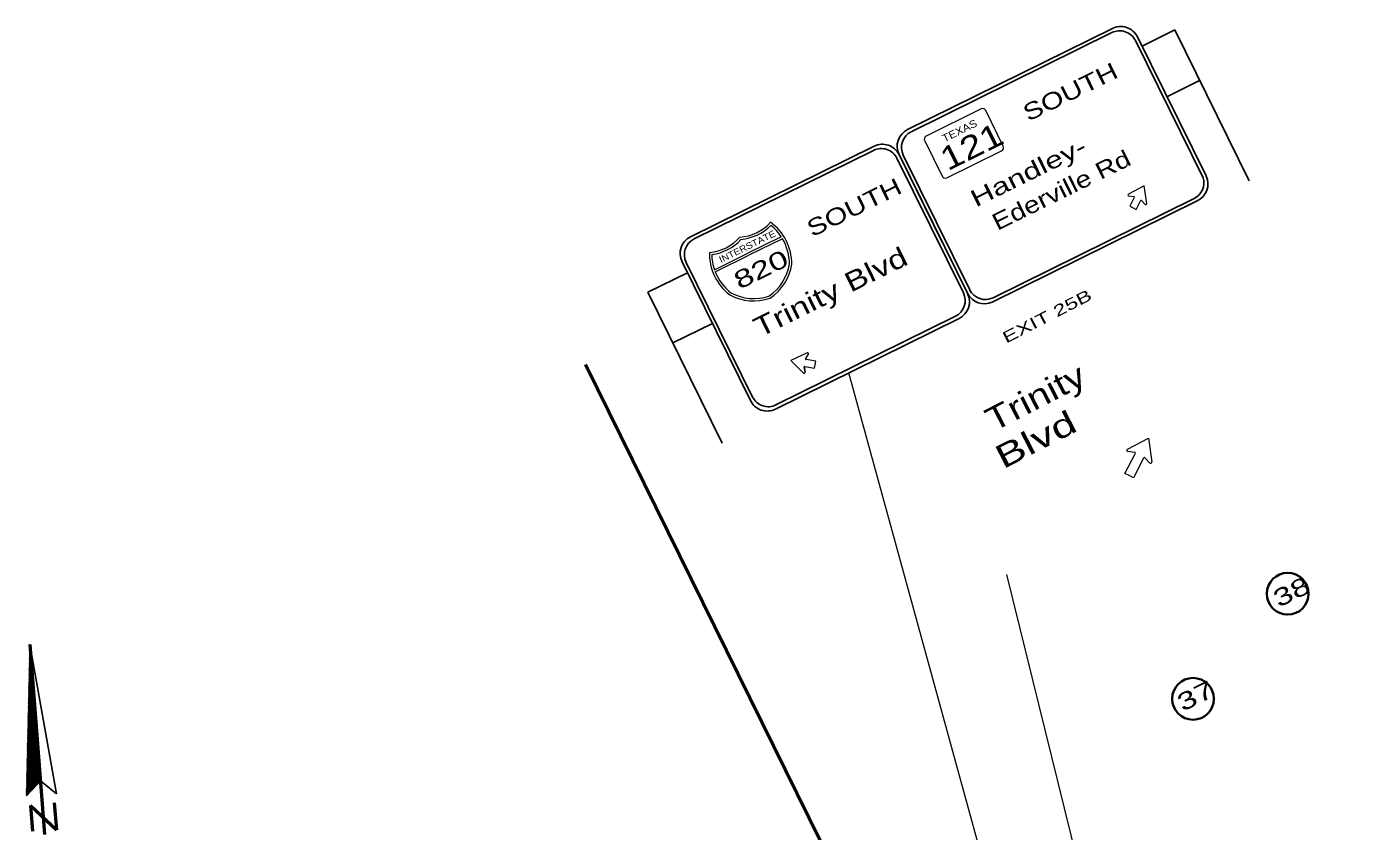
# Model space of a CAD drawing. Extents: x 2356431 to 2371438, y 6972864 to 6982525.
# Drawn here: x 2364824 to 2365891, y 6980028 to 6980677 of the extents above; entities that cross this region are included whole.
import ezdxf
from ezdxf.enums import TextEntityAlignment as Align

# ---------------------------------------------------------------- set-up
doc = ezdxf.new("R2010")
doc.units = 0
doc.header["$LTSCALE"] = 5.6
for name, color, linetype, lineweight in [('1', 7, 'Continuous', 25), ('17', 7, 'Continuous', 35), ('48', 7, 'Continuous', 25), ('53', 7, 'Continuous', 13)]:
    doc.layers.add(name, color=color, linetype=linetype, lineweight=lineweight)

msp = doc.modelspace()

# ---------------------------------------------------------------- linework, layer by layer
at = {"layer": '1'}
for p, q in [((2365699.561, 6980675.512), (2365534.335, 6980593.967)), ((2365699.121, 6980672.152), (2365537.267, 6980592.281)), ((2365772.637, 6980555.025), (2365718.004, 6980665.739)), ((2365719.704, 6980668.682), (2365774.934, 6980556.768)), ((2365723.334, 6980661.327), (2365749.68, 6980674.33)), ((2365749.68, 6980674.33), (2365809.681, 6980552.756)), ((2365743.473, 6980620.519), (2365769.82, 6980633.522)), ((2365359.337, 6980507.547), (2365507.416, 6980580.622)), ((2365362.262, 6980505.855), (2365506.979, 6980577.267)), ((2365525.812, 6980570.889), (2365579.367, 6980462.366)), ((2365527.494, 6980573.816), (2365582.881, 6980461.58)), ((2365527.494, 6980573.816), (2365562.301, 6980503.282)), ((2365530.863, 6980573.374), (2365584.421, 6980464.846)), ((2365603.297, 6980458.49), (2365765.316, 6980538.447)), ((2365602.584, 6980455.002), (2365767.8, 6980536.548)), ((2365352.536, 6980487.453), (2365407.746, 6980375.561)), ((2365409.438, 6980378.486), (2365355.874, 6980487.022)), ((2365356.9, 6980478.608), (2365325.014, 6980462.872)), ((2365325.014, 6980462.872), (2365385.015, 6980341.298)), ((2365575.911, 6980441.846), (2365427.831, 6980368.762)), ((2365572.989, 6980443.533), (2365428.272, 6980372.109)), ((2365377.036, 6980437.799), (2365345.154, 6980422.062)), ((2365451.015, 6980402.503), (2365451.716, 6980398.425))]:
    msp.add_line(p, q, dxfattribs=at)
at = {"layer": '1', "lineweight": 13}
for p, q in [((2365593.569, 6980610.607), (2365549.407, 6980588.816)), ((2365611.46, 6980580.685), (2365597.331, 6980609.33)), ((2365548.134, 6980585.048), (2365562.262, 6980556.405)), ((2365566.03, 6980555.132), (2365610.188, 6980576.918)), ((2365432.468, 6980507.644), (2365405.567, 6980494.364)), ((2365433.476, 6980506.029), (2365406.406, 6980492.671)), ((2365378.668, 6980481.086), (2365405.567, 6980494.364)), ((2365379.318, 6980479.296), (2365406.406, 6980492.671)), ((2365593.998, 6980008.645), (2365486.909, 6980397.919)), ((2365727.493, 6979776.865), (2365614.297, 6980235.555)), ((2364826.68, 6980173.822), (2364827.153, 6980174.375)), ((2364826.692, 6980174.318), (2364827.122, 6980174.817)), ((2364826.702, 6980174.816), (2364827.086, 6980175.262)), ((2364826.714, 6980175.312), (2364827.051, 6980175.706)), ((2364826.726, 6980175.81), (2364827.017, 6980176.151)), ((2364826.736, 6980176.308), (2364826.982, 6980176.594)), ((2364826.747, 6980176.805), (2364826.951, 6980177.038)), ((2364826.76, 6980177.298), (2364826.913, 6980177.483)), ((2364826.771, 6980177.799), (2364826.882, 6980177.925)), ((2364826.783, 6980178.296), (2364826.847, 6980178.371)), ((2364826.793, 6980178.791), (2364826.812, 6980178.815)), ((2364826.412, 6980161.892), (2364827.974, 6980163.716)), ((2364826.422, 6980162.39), (2364827.939, 6980164.158)), ((2364826.435, 6980162.887), (2364827.906, 6980164.605)), ((2364826.445, 6980163.386), (2364827.871, 6980165.045)), ((2364826.458, 6980163.882), (2364827.838, 6980165.492)), ((2364826.469, 6980164.379), (2364827.804, 6980165.935)), ((2364826.477, 6980164.875), (2364827.769, 6980166.38)), ((2364826.49, 6980165.371), (2364827.735, 6980166.824)), ((2364826.502, 6980165.869), (2364827.7, 6980167.269)), ((2364826.514, 6980166.365), (2364827.666, 6980167.714)), ((2364826.525, 6980166.863), (2364827.631, 6980168.158)), ((2364826.536, 6980167.362), (2364827.599, 6980168.601)), ((2364826.545, 6980167.858), (2364827.565, 6980169.046)), ((2364826.559, 6980168.356), (2364827.529, 6980169.486)), ((2364826.569, 6980168.853), (2364827.496, 6980169.936)), ((2364826.581, 6980169.349), (2364827.46, 6980170.377)), ((2364826.588, 6980169.846), (2364827.427, 6980170.823)), ((2364826.603, 6980170.343), (2364827.392, 6980171.265)), ((2364826.614, 6980170.841), (2364827.36, 6980171.709)), ((2364826.624, 6980171.339), (2364827.325, 6980172.154)), ((2364826.636, 6980171.836), (2364827.29, 6980172.596)), ((2364826.649, 6980172.334), (2364827.257, 6980173.042)), ((2364826.658, 6980172.83), (2364827.221, 6980173.486)), ((2364826.669, 6980173.326), (2364827.189, 6980173.931)), ((2364826.142, 6980149.964), (2364828.794, 6980153.057)), ((2364826.154, 6980150.462), (2364828.759, 6980153.502)), ((2364826.164, 6980150.961), (2364828.725, 6980153.946)), ((2364826.178, 6980151.456), (2364828.692, 6980154.389)), ((2364826.188, 6980151.952), (2364828.656, 6980154.835)), ((2364826.2, 6980152.449), (2364828.623, 6980155.278)), ((2364826.21, 6980152.947), (2364828.59, 6980155.723)), ((2364826.222, 6980153.445), (2364828.555, 6980156.165)), ((2364826.233, 6980153.943), (2364828.52, 6980156.609)), ((2364826.244, 6980154.44), (2364828.486, 6980157.057)), ((2364826.256, 6980154.936), (2364828.453, 6980157.498)), ((2364826.267, 6980155.432), (2364828.417, 6980157.943)), ((2364826.277, 6980155.931), (2364828.385, 6980158.385)), ((2364826.288, 6980156.424), (2364828.349, 6980158.83)), ((2364826.299, 6980156.923), (2364828.316, 6980159.275)), ((2364826.313, 6980157.419), (2364828.28, 6980159.718)), ((2364826.322, 6980157.918), (2364828.247, 6980160.162)), ((2364826.335, 6980158.416), (2364828.214, 6980160.608)), ((2364826.344, 6980158.913), (2364828.178, 6980161.051)), ((2364826.356, 6980159.409), (2364828.145, 6980161.496)), ((2364826.367, 6980159.905), (2364828.11, 6980161.939)), ((2364826.38, 6980160.404), (2364828.077, 6980162.383)), ((2364826.39, 6980160.9), (2364828.043, 6980162.828)), ((2364826.401, 6980161.396), (2364828.008, 6980163.271)), ((2364825.874, 6980138.036), (2364829.612, 6980142.398)), ((2364825.885, 6980138.533), (2364829.581, 6980142.844)), ((2364825.898, 6980139.03), (2364829.546, 6980143.286)), ((2364825.909, 6980139.527), (2364829.512, 6980143.731)), ((2364825.922, 6980140.024), (2364829.477, 6980144.174)), ((2364825.929, 6980140.522), (2364829.442, 6980144.618)), ((2364825.944, 6980141.019), (2364829.41, 6980145.062)), ((2364825.953, 6980141.517), (2364829.374, 6980145.507)), ((2364825.964, 6980142.014), (2364829.342, 6980145.95)), ((2364825.977, 6980142.511), (2364829.308, 6980146.397)), ((2364825.988, 6980143.008), (2364829.274, 6980146.837)), ((2364825.998, 6980143.505), (2364829.237, 6980147.286)), ((2364826.009, 6980143.999), (2364829.202, 6980147.728)), ((2364826.019, 6980144.497), (2364829.171, 6980148.174)), ((2364826.031, 6980144.995), (2364829.135, 6980148.615)), ((2364826.043, 6980145.492), (2364829.103, 6980149.061)), ((2364826.055, 6980145.99), (2364829.068, 6980149.505)), ((2364826.065, 6980146.486), (2364829.034, 6980149.948)), ((2364826.077, 6980146.983), (2364828.998, 6980150.392)), ((2364826.089, 6980147.479), (2364828.964, 6980150.837)), ((2364826.099, 6980147.976), (2364828.931, 6980151.28)), ((2364826.108, 6980148.471), (2364828.895, 6980151.727)), ((2364826.121, 6980148.969), (2364828.863, 6980152.168)), ((2364826.132, 6980149.467), (2364828.829, 6980152.614)), ((2364825.607, 6980126.11), (2364830.433, 6980131.738)), ((2364825.616, 6980126.605), (2364830.398, 6980132.184)), ((2364825.628, 6980127.102), (2364830.367, 6980132.629)), ((2364825.641, 6980127.598), (2364830.33, 6980133.072)), ((2364825.65, 6980128.096), (2364830.299, 6980133.516)), ((2364825.664, 6980128.593), (2364830.264, 6980133.96)), ((2364825.675, 6980129.09), (2364830.23, 6980134.406)), ((2364825.687, 6980129.585), (2364830.194, 6980134.849)), ((2364825.696, 6980130.084), (2364830.16, 6980135.294)), ((2364825.706, 6980130.58), (2364830.127, 6980135.737)), ((2364825.72, 6980131.076), (2364830.091, 6980136.181)), ((2364825.729, 6980131.575), (2364830.06, 6980136.626)), ((2364825.74, 6980132.073), (2364830.025, 6980137.068)), ((2364825.751, 6980132.571), (2364829.991, 6980137.513)), ((2364825.762, 6980133.067), (2364829.955, 6980137.957)), ((2364825.773, 6980133.564), (2364829.92, 6980138.402)), ((2364825.785, 6980134.06), (2364829.888, 6980138.847)), ((2364825.797, 6980134.557), (2364829.852, 6980139.289)), ((2364825.809, 6980135.053), (2364829.82, 6980139.734)), ((2364825.82, 6980135.552), (2364829.785, 6980140.18)), ((2364825.831, 6980136.048), (2364829.751, 6980140.622)), ((2364825.841, 6980136.543), (2364829.716, 6980141.066)), ((2364825.853, 6980137.043), (2364829.681, 6980141.508)), ((2364825.864, 6980137.541), (2364829.649, 6980141.956)), ((2364825.337, 6980114.179), (2364831.255, 6980121.082)), ((2364825.351, 6980114.676), (2364831.22, 6980121.526)), ((2364825.359, 6980115.176), (2364831.185, 6980121.969)), ((2364825.371, 6980115.67), (2364831.15, 6980122.413)), ((2364825.382, 6980116.169), (2364831.117, 6980122.858)), ((2364825.392, 6980116.667), (2364831.084, 6980123.301)), ((2364825.406, 6980117.161), (2364831.048, 6980123.748)), ((2364825.416, 6980117.658), (2364831.015, 6980124.191)), ((2364825.428, 6980118.154), (2364830.981, 6980124.635)), ((2364825.44, 6980118.653), (2364830.945, 6980125.077)), ((2364825.449, 6980119.151), (2364830.911, 6980125.525)), ((2364825.462, 6980119.647), (2364830.876, 6980125.967)), ((2364825.472, 6980120.143), (2364830.845, 6980126.409)), ((2364825.483, 6980120.641), (2364830.809, 6980126.856)), ((2364825.495, 6980121.139), (2364830.776, 6980127.299)), ((2364825.505, 6980121.634), (2364830.742, 6980127.744)), ((2364825.52, 6980122.131), (2364830.708, 6980128.186)), ((2364825.527, 6980122.629), (2364830.671, 6980128.629)), ((2364825.542, 6980123.124), (2364830.638, 6980129.078)), ((2364825.551, 6980123.624), (2364830.606, 6980129.519)), ((2364825.562, 6980124.119), (2364830.569, 6980129.963)), ((2364825.573, 6980124.619), (2364830.537, 6980130.406)), ((2364825.584, 6980125.115), (2364830.503, 6980130.85)), ((2364825.596, 6980125.61), (2364830.469, 6980131.295)), ((2364825.068, 6980102.252), (2364832.073, 6980110.421)), ((2364825.082, 6980102.748), (2364832.04, 6980110.868)), ((2364825.091, 6980103.244), (2364832.005, 6980111.31)), ((2364825.102, 6980103.741), (2364831.972, 6980111.757)), ((2364825.115, 6980104.241), (2364831.939, 6980112.2)), ((2364825.125, 6980104.733), (2364831.902, 6980112.644)), ((2364825.134, 6980105.232), (2364831.868, 6980113.087)), ((2364825.149, 6980105.731), (2364831.834, 6980113.529)), ((2364825.161, 6980106.228), (2364831.801, 6980113.977)), ((2364825.171, 6980106.722), (2364831.765, 6980114.419)), ((2364825.182, 6980107.222), (2364831.733, 6980114.864)), ((2364825.192, 6980107.719), (2364831.7, 6980115.309)), ((2364825.204, 6980108.215), (2364831.663, 6980115.753)), ((2364825.215, 6980108.713), (2364831.628, 6980116.201)), ((2364825.226, 6980109.208), (2364831.595, 6980116.641)), ((2364825.237, 6980109.706), (2364831.562, 6980117.085)), ((2364825.248, 6980110.203), (2364831.526, 6980117.53)), ((2364825.262, 6980110.702), (2364831.494, 6980117.973)), ((2364825.269, 6980111.198), (2364831.46, 6980118.418)), ((2364825.283, 6980111.695), (2364831.424, 6980118.859)), ((2364825.294, 6980112.19), (2364831.39, 6980119.307)), ((2364825.306, 6980112.689), (2364831.356, 6980119.749)), ((2364825.317, 6980113.187), (2364831.323, 6980120.195)), ((2364825.327, 6980113.683), (2364831.287, 6980120.636)), ((2364824.801, 6980090.324), (2364832.895, 6980099.765)), ((2364824.811, 6980090.818), (2364832.858, 6980100.21)), ((2364824.823, 6980091.317), (2364832.827, 6980100.652)), ((2364824.834, 6980091.813), (2364832.791, 6980101.099)), ((2364824.845, 6980092.308), (2364832.759, 6980101.542)), ((2364824.855, 6980092.807), (2364832.722, 6980101.986)), ((2364824.867, 6980093.304), (2364832.69, 6980102.431)), ((2364824.879, 6980093.802), (2364832.657, 6980102.873)), ((2364824.89, 6980094.299), (2364832.619, 6980103.318)), ((2364824.901, 6980094.795), (2364832.585, 6980103.761)), ((2364824.913, 6980095.291), (2364832.551, 6980104.205)), ((2364824.924, 6980095.789), (2364832.519, 6980104.65)), ((2364824.934, 6980096.286), (2364832.483, 6980105.093)), ((2364824.946, 6980096.786), (2364832.451, 6980105.539)), ((2364824.956, 6980097.283), (2364832.416, 6980105.981)), ((2364824.968, 6980097.779), (2364832.38, 6980106.427)), ((2364824.98, 6980098.275), (2364832.346, 6980106.869)), ((2364824.988, 6980098.773), (2364832.313, 6980107.313)), ((2364825.003, 6980099.272), (2364832.28, 6980107.759)), ((2364825.011, 6980099.766), (2364832.244, 6980108.201)), ((2364825.025, 6980100.264), (2364832.212, 6980108.649)), ((2364825.035, 6980100.761), (2364832.178, 6980109.089)), ((2364825.046, 6980101.257), (2364832.141, 6980109.534)), ((2364825.059, 6980101.756), (2364832.107, 6980109.981)), ((2364824.529, 6980078.394), (2364833.716, 6980089.106)), ((2364824.543, 6980078.891), (2364833.678, 6980089.551)), ((2364824.553, 6980079.388), (2364833.647, 6980089.993)), ((2364824.565, 6980079.884), (2364833.61, 6980090.438)), ((2364824.574, 6980080.383), (2364833.576, 6980090.883)), ((2364824.588, 6980080.879), (2364833.544, 6980091.328)), ((2364824.599, 6980081.378), (2364833.508, 6980091.77)), ((2364824.609, 6980081.873), (2364833.477, 6980092.215)), ((2364824.619, 6980082.371), (2364833.44, 6980092.657)), ((2364824.632, 6980082.869), (2364833.408, 6980093.102)), ((2364824.643, 6980083.366), (2364833.373, 6980093.547)), ((2364824.655, 6980083.862), (2364833.337, 6980093.99)), ((2364824.666, 6980084.358), (2364833.304, 6980094.435)), ((2364824.679, 6980084.854), (2364833.269, 6980094.879)), ((2364824.69, 6980085.355), (2364833.237, 6980095.322)), ((2364824.701, 6980085.851), (2364833.2, 6980095.769)), ((2364824.71, 6980086.347), (2364833.168, 6980096.211)), ((2364824.721, 6980086.843), (2364833.134, 6980096.659)), ((2364824.732, 6980087.338), (2364833.097, 6980097.1)), ((2364824.746, 6980087.837), (2364833.066, 6980097.545)), ((2364824.754, 6980088.334), (2364833.029, 6980097.99)), ((2364824.766, 6980088.831), (2364832.997, 6980098.432)), ((2364824.779, 6980089.33), (2364832.962, 6980098.877)), ((2364824.79, 6980089.826), (2364832.929, 6980099.323)), ((2364824.263, 6980066.467), (2364834.534, 6980078.448)), ((2364824.274, 6980066.964), (2364834.501, 6980078.891)), ((2364824.286, 6980067.459), (2364834.465, 6980079.335)), ((2364824.295, 6980067.957), (2364834.432, 6980079.78)), ((2364824.307, 6980068.455), (2364834.398, 6980080.224)), ((2364824.319, 6980068.952), (2364834.365, 6980080.669)), ((2364824.329, 6980069.448), (2364834.327, 6980081.114)), ((2364824.343, 6980069.943), (2364834.294, 6980081.556)), ((2364824.351, 6980070.441), (2364834.261, 6980082.001)), ((2364824.366, 6980070.937), (2364834.226, 6980082.446)), ((2364824.374, 6980071.436), (2364834.193, 6980082.889)), ((2364824.385, 6980071.934), (2364834.159, 6980083.334)), ((2364824.396, 6980072.43), (2364834.124, 6980083.776)), ((2364824.409, 6980072.928), (2364834.089, 6980084.221)), ((2364824.421, 6980073.423), (2364834.055, 6980084.668)), ((2364824.432, 6980073.921), (2364834.021, 6980085.112)), ((2364824.44, 6980074.416), (2364833.986, 6980085.552)), ((2364824.453, 6980074.914), (2364833.954, 6980085.999)), ((2364824.464, 6980075.411), (2364833.918, 6980086.443)), ((2364824.474, 6980075.908), (2364833.886, 6980086.885)), ((2364824.488, 6980076.405), (2364833.849, 6980087.329)), ((2364824.497, 6980076.904), (2364833.815, 6980087.774)), ((2364824.51, 6980077.4), (2364833.783, 6980088.219)), ((2364824.521, 6980077.896), (2364833.747, 6980088.662)), ((2364824.05, 6980057.02), (2364835.183, 6980070.01)), ((2364824.061, 6980057.519), (2364835.15, 6980070.453)), ((2364824.071, 6980058.015), (2364835.116, 6980070.899)), ((2364824.085, 6980058.513), (2364835.081, 6980071.343)), ((2364824.095, 6980059.01), (2364835.045, 6980071.787)), ((2364824.108, 6980059.508), (2364835.011, 6980072.232)), ((2364824.117, 6980060.004), (2364834.98, 6980072.673)), ((2364824.128, 6980060.5), (2364834.943, 6980073.12)), ((2364824.139, 6980060.997), (2364834.911, 6980073.563)), ((2364824.151, 6980061.493), (2364834.876, 6980074.007)), ((2364824.163, 6980061.991), (2364834.842, 6980074.452)), ((2364824.174, 6980062.487), (2364834.806, 6980074.895)), ((2364824.184, 6980062.986), (2364834.772, 6980075.339)), ((2364824.194, 6980063.482), (2364834.74, 6980075.782)), ((2364824.206, 6980063.981), (2364834.704, 6980076.228)), ((2364824.219, 6980064.478), (2364834.671, 6980076.673)), ((2364824.23, 6980064.976), (2364834.637, 6980077.116)), ((2364824.242, 6980065.472), (2364834.603, 6980077.56)), ((2364824.252, 6980065.968), (2364834.567, 6980078.001)), ((2364829.453, 6980062.84), (2364835.218, 6980069.566))]:
    msp.add_line(p, q, dxfattribs=at)
at = {"layer": '1', "lineweight": 53}
for p, q in [((2365274.698, 6980404.566), (2366089.834, 6978752.959)), ((2364826.798, 6980179.006), (2364838.576, 6980025.886)), ((2364827.233, 6980049.348), (2364828.832, 6980028.573)), ((2364827.233, 6980049.348), (2364848.148, 6980029.812)), ((2364846.474, 6980051.567), (2364848.148, 6980029.812))]:
    msp.add_line(p, q, dxfattribs=at)
at = {"layer": '1', "lineweight": 13}
msp.add_lwpolyline([(2364824.051, 6980056.983), (2364835.25, 6980069.127), (2364826.798, 6980179.006)], close=True, dxfattribs=at)
at = {"layer": '1'}
msp.add_lwpolyline([(2364848.179, 6980058.841), (2364835.25, 6980069.127), (2364826.798, 6980179.006)], close=True, dxfattribs=at)
for centre, radius, start, end in [((2365706.217, 6980662.02), 15.049, 26.26806, 117.68557), ((2365705.363, 6980659.5), 14.108, 26.26806, 116.26806), ((2365540.997, 6980580.475), 15.049, 116.26806, 206.26806), ((2365543.516, 6980579.621), 14.108, 116.26806, 206.26806), ((2365514.054, 6980567.173), 15.001, 26.26895, 116.26895), ((2365513.202, 6980564.662), 14.063, 26.26895, 116.26895), ((2365759.072, 6980551.098), 14.108, 296.26806, 16.67271), ((2365761.417, 6980550.176), 15.049, 295.0985, 24.9686), ((2365716.695, 6980539.465), 0.506, 332.82583, 82.80894), ((2365722.64, 6980536.413), 0.506, 42.84273, 152.82583), ((2365365.976, 6980494.094), 15.001, 116.26895, 206.26895), ((2365368.487, 6980493.243), 14.063, 116.26895, 206.26895), ((2365597.053, 6980471.14), 14.108, 206.26806, 296.26806), ((2365566.763, 6980456.142), 14.063, 296.26895, 26.26895), ((2365569.274, 6980455.291), 15.001, 296.26895, 26.26895), ((2365596.2, 6980468.631), 15.049, 206.26806, 295.0985), ((2365452.703, 6980409.177), 0.506, 149.72682, 259.70992), ((2365451.51, 6980402.601), 0.506, 79.70992, 189.69303), ((2365422.048, 6980384.723), 14.063, 206.26895, 296.26895), ((2365421.196, 6980382.211), 15.001, 206.26895, 296.26895)]:
    msp.add_arc(centre, radius, start, end, dxfattribs=at)
at = {"layer": '1', "lineweight": 13}
for centre, radius, start, end in [((2365594.809, 6980608.082), 2.813, 26.26788, 116.26788), ((2365550.654, 6980586.29), 2.813, 116.26788, 206.26788), ((2365608.942, 6980579.447), 2.813, 296.26788, 26.26788), ((2365564.787, 6980557.655), 2.813, 206.26788, 296.26788), ((2365396.977, 6980543.286), 35.984, 273.44845, 318.29876), ((2365396.977, 6980543.286), 37.874, 274.64636, 315.6432), ((2365399.085, 6980485.478), 41.954, 0.13125, 53.83362), ((2365399.085, 6980485.478), 40.064, 33.57769, 51.44245), ((2365371.948, 6980530.933), 35.984, 274.23736, 319.08768), ((2365371.948, 6980530.933), 37.874, 276.89292, 317.88976), ((2365399.085, 6980485.478), 40.064, 0.34779, 30.85977), ((2365416.55, 6980494.097), 41.954, 178.7025, 232.40488), ((2365416.55, 6980494.097), 40.064, 181.09368, 198.95843), ((2365400.845, 6980491.958), 38.808, 304.1061, 350.75248), ((2365400.845, 6980491.958), 40.698, 303.73996, 350.97586), ((2365416.55, 6980494.097), 40.064, 201.67636, 232.18834), ((2365410.336, 6980496.642), 40.698, 241.56027, 288.79617), ((2365410.336, 6980496.642), 38.808, 241.78364, 288.43003)]:
    msp.add_arc(centre, radius, start, end, dxfattribs=at)
at = {"layer": '17'}
for centre in [(2365840.775, 6980219.98), (2365764.489, 6980135.292)]:
    msp.add_circle(centre, 16.828, dxfattribs=at)
at = {"layer": '53'}
for p, q in [((2365712.633, 6980540.483), (2365716.76, 6980539.946)), ((2365723.017, 6980536.745), (2365725.828, 6980533.708)), ((2365727.135, 6980534.338), (2365727.123, 6980534.361)), ((2365452.28, 6980409.418), (2365454.365, 6980413.02)), ((2365451.713, 6980398.432), (2365451.618, 6980403.101)), ((2365717.374, 6980333.812), (2365711.926, 6980334.559)), ((2365709.562, 6980316.988), (2365717.939, 6980332.834)), ((2365729.43, 6980325.334), (2365725.714, 6980329.447))]:
    msp.add_line(p, q, dxfattribs=at)
for points in [[(2365727.123, 6980534.361), (2365725.133, 6980548.589), (2365712.404, 6980541.917)], [(2365717.14, 6980539.219), (2365713.576, 6980532.294), (2365716.097, 6980531.003), (2365718.625, 6980529.716), (2365722.177, 6980536.631)], [(2365453.367, 6980414.073), (2365440.328, 6980408.028), (2365450.41, 6980397.795)], [(2365451.618, 6980403.101), (2365459.267, 6980401.714), (2365459.783, 6980404.502), (2365460.292, 6980407.29), (2365452.627, 6980408.674)], [(2365711.636, 6980336.475), (2365728.66, 6980345.227), (2365731.154, 6980326.233)], [(2365724.562, 6980329.323), (2365716.349, 6980313.444), (2365712.915, 6980315.235), (2365709.562, 6980316.988)]]:
    msp.add_lwpolyline(points, dxfattribs=at)
for centre, radius, start, end in [((2365712.739, 6980541.235), 0.759, 117.56432, 262.94546), ((2365726.383, 6980534.231), 0.759, 222.7062, 8.08734), ((2365453.704, 6980413.393), 0.759, 329.59029, 114.97143), ((2365450.965, 6980398.303), 0.759, 224.44842, 9.82956), ((2365712.079, 6980335.562), 1.012, 117.00557, 262.38671), ((2365717.327, 6980333.152), 0.675, 332.26707, 82.25018), ((2365725.211, 6980329.007), 0.675, 42.28397, 152.26708), ((2365730.171, 6980326.05), 1.012, 222.14744, 7.52858)]:
    msp.add_arc(centre, radius, start, end, dxfattribs=at)

# ---------------------------------------------------------------- texts
at = {"layer": '1'}
for s, height, rotation, width, p in [('SOUTH', 13.5, 26.269, 1.3, (2365668.497, 6980618.449)), ('Handley-', 13.5, 26.269, 1.4, (2365634.753, 6980553.581)), ('Ederville Rd', 13.5, 26.269, 1.25, (2365661.259, 6980539.201)), ('SOUTH', 13.5, 26.269, 1.3, (2365494.246, 6980525.263)), ('Trinity Blvd', 15.68, 26.268, 1.3, (2365475.594, 6980456.141))]:
    msp.add_text(s, height=height, rotation=rotation, dxfattribs=dict(at, width=width)).set_placement(p, align=Align.CENTER)
for s, height, width, p in [('TEXAS', 6, 1.15, (2365564.043, 6980583.653)), ('121', 18.75, 1.25, (2365566.654, 6980560.353)), ('INTERSTATE', 5.198, 1.15, (2365383.981, 6980486.411)), ('820', 14.18, 1.45, (2365398.776, 6980464.874))]:
    msp.add_text(s, height=height, rotation=26.268, dxfattribs=dict(at, width=width)).set_placement(p)
at = {"layer": '17', "width": 1.45}
for s, p in [('38', (2365847.07, 6980215.281)), ('37', (2365769.613, 6980131.419))]:
    msp.add_text(s, height=14, rotation=26.268, dxfattribs=at).set_placement(p, align=Align.CENTER)
at = {"layer": '48'}
for s, height, width, p in [('EXIT 25B', 9.184, 1.5, (2365648.878, 6980439.527)), ('Trinity', 18.9, 1.25, (2365641.655, 6980369.877)), ('Blvd', 18.9, 1.4, (2365641.99, 6980335.902))]:
    msp.add_text(s, height=height, rotation=27.267, dxfattribs=dict(at, width=width)).set_placement(p, align=Align.CENTER)

doc.saveas('drawing.dxf')
